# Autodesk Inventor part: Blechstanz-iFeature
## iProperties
Created: 2009-02
Part Number: Blechstanz-iFeature
Material: 1.0037 St 37-2
Document SubType Name: Modeling
Density: 1 g/cm^3
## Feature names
1. Extrusion2
2. Wandstärke1
3. Extrusion3
